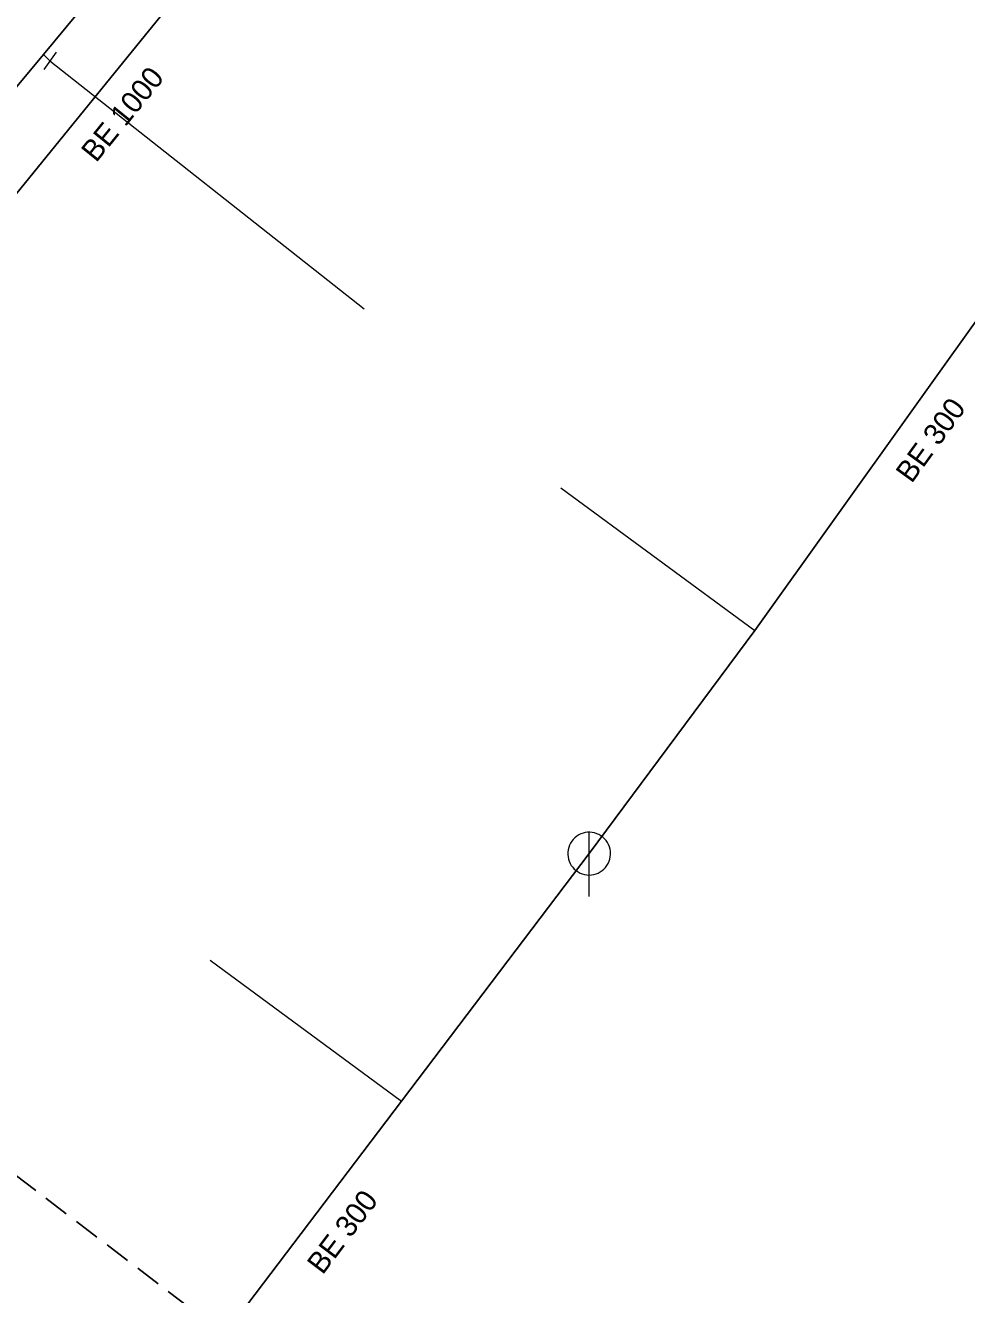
# Model space of a CAD drawing. Extents: x -791337 to -790755, y -988454 to -987923.
# Drawn here: x -790993.7 to -790949.7, y -988336.6 to -988277.2 of the extents above; entities that cross this region are included whole.
import ezdxf

# ---------------------------------------------------------------- set-up
doc = ezdxf.new("R2010")
doc.units = 0
doc.header["$LTSCALE"] = 0.4
doc.linetypes.add('MEDIUM_DASHED', pattern=[4.5, 3, -1.5])
for name, color, linetype, lineweight in [('1', 7, 'Continuous', 13), ('11', 7, 'Continuous', 13), ('13', 7, 'Continuous', 13), ('14', 7, 'Continuous', 25), ('17', 7, 'Continuous', 25), ('22', 7, 'Continuous', 13), ('34', 7, 'Continuous', 13), ('63', 7, 'MEDIUM_DASHED', 25)]:
    doc.layers.add(name, color=color, linetype=linetype, lineweight=lineweight)

msp = doc.modelspace()

# ---------------------------------------------------------------- linework, layer by layer
at = {"layer": '11'}
for p, q in [((-790968.677, -988298.831), (-790959.611, -988305.497)), ((-790985.079, -988320.912), (-790976.131, -988327.509))]:
    msp.add_line(p, q, dxfattribs=at)
at = {"layer": '13'}
msp.add_line((-790992.573, -988278.877), (-790977.886, -988290.458), dxfattribs=at)
at = {"layer": '14', "lineweight": 13}
msp.add_line((-790992.881, -988278.57), (-790992.573, -988278.877), dxfattribs=at)
at = {"layer": '14'}
for points in [[(-791005.342, -988298.738), (-790994.723, -988285.809), (-790974.239, -988260.57)], [(-790967.359, -988315.936), (-790959.611, -988305.497), (-790944.69, -988284.64)], [(-790991.827, -988348.214), (-790987.278, -988342.213), (-790976.131, -988327.509), (-790967.359, -988315.936)]]:
    msp.add_lwpolyline(points, dxfattribs=at)
at = {"layer": '17'}
msp.add_lwpolyline([(-790965.795, -988245.864), (-790968.875, -988249.407), (-790981.155, -988264.329), (-790987.956, -988272.624), (-790992.881, -988278.57), (-791010.125, -988299.302)], dxfattribs=at)
at = {"layer": '22'}
msp.add_line((-790967.359, -988317.937), (-790967.358, -988314.937), dxfattribs=at)
msp.add_lwpolyline([(-790966.359, -988315.937), (-790966.364, -988315.828), (-790966.382, -988315.72), (-790966.412, -988315.614), (-790966.452, -988315.513), (-790966.504, -988315.416), (-790966.566, -988315.326), (-790966.638, -988315.243), (-790966.718, -988315.169), (-790966.806, -988315.103), (-790966.9, -988315.048), (-790967, -988315.003), (-790967.105, -988314.97), (-790967.212, -988314.948), (-790967.321, -988314.938), (-790967.431, -988314.94), (-790967.539, -988314.954), (-790967.646, -988314.979), (-790967.749, -988315.016), (-790967.847, -988315.065), (-790967.939, -988315.123), (-790968.025, -988315.192), (-790968.102, -988315.269), (-790968.171, -988315.355), (-790968.23, -988315.447), (-790968.278, -988315.545), (-790968.315, -988315.648), (-790968.341, -988315.755), (-790968.355, -988315.863), (-790968.358, -988315.973), (-790968.348, -988316.082), (-790968.327, -988316.189), (-790968.293, -988316.293), (-790968.249, -988316.393), (-790968.194, -988316.488), (-790968.128, -988316.576), (-790968.054, -988316.656), (-790967.971, -988316.728), (-790967.881, -988316.79), (-790967.785, -988316.842), (-790967.683, -988316.883), (-790967.578, -988316.913), (-790967.47, -988316.931), (-790967.36, -988316.937), (-790967.251, -988316.931), (-790967.143, -988316.913), (-790967.038, -988316.884), (-790966.936, -988316.843), (-790966.839, -988316.791), (-790966.749, -988316.729), (-790966.666, -988316.658), (-790966.591, -988316.578), (-790966.526, -988316.49), (-790966.47, -988316.396), (-790966.426, -988316.296), (-790966.392, -988316.192), (-790966.37, -988316.084), (-790966.36, -988315.975)], close=True, dxfattribs=at)
at = {"layer": '34'}
msp.add_line((-790992.28, -988278.471), (-790992.866, -988279.281), dxfattribs=at)
at = {"layer": '63'}
msp.add_lwpolyline([(-791231.02, -987923.132), (-790755.118, -988202.253), (-790755.118, -988202.253), (-790903.053, -988400.429), (-790903.053, -988400.429), (-791331.504, -988073.857), (-791331.504, -988073.857)], close=True, dxfattribs=at)

# ---------------------------------------------------------------- texts
at = {"layer": '1'}
for s, rotation, p in [('BE 1000 ', 51, (-790990.412, -988283.662)), ('BE 300', 54, (-790952.28, -988298.662)), ('BE 300', 53, (-790979.822, -988335.664))]:
    msp.add_text(s, height=1, rotation=rotation, dxfattribs=at).set_placement(p)

doc.saveas('drawing.dxf')
